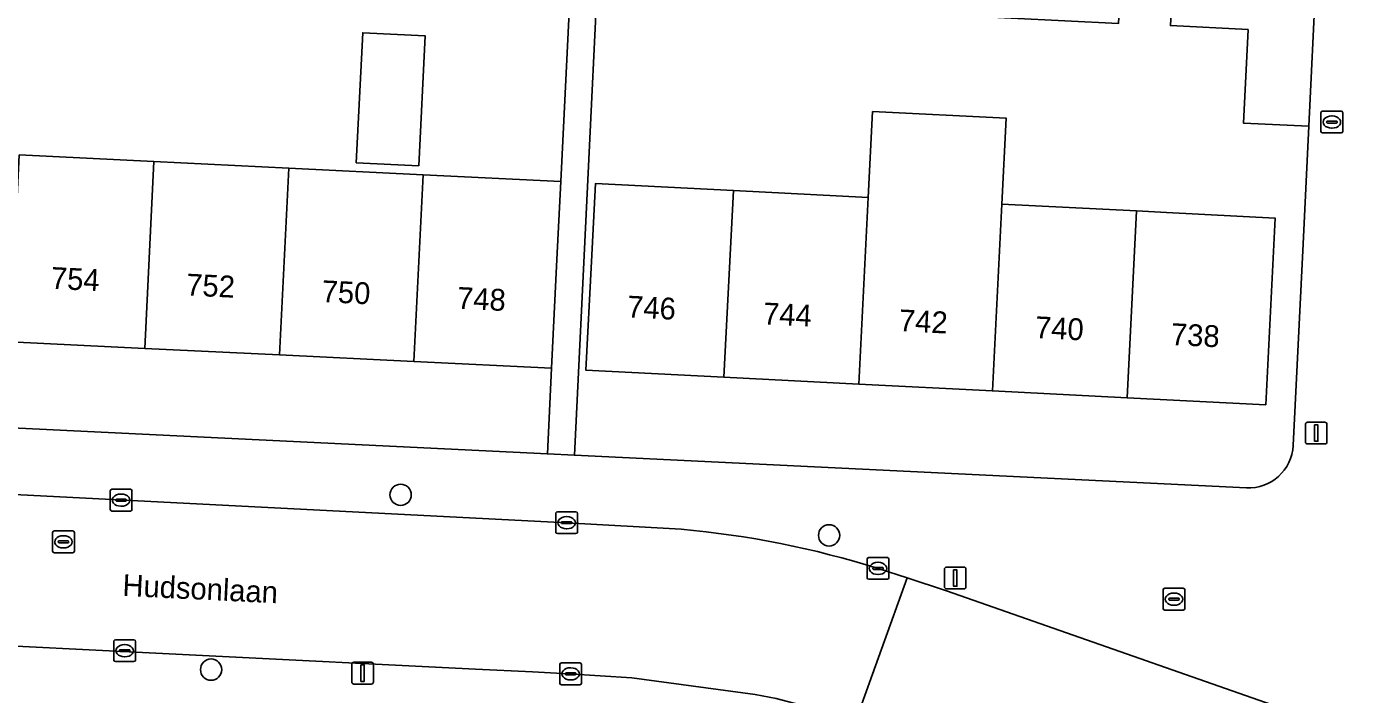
# Model space of a CAD drawing. Extents: x 161248 to 161848, y 384871 to 385383.
# Drawn here: x 161697.1 to 161757.8, y 385313.6 to 385344.3 of the extents above; entities that cross this region are included whole.
import ezdxf

# ---------------------------------------------------------------- set-up
doc = ezdxf.new("R2010")
doc.units = 0
for name, color, linetype in [('IMGEO_Boom', 7, 'Continuous'), ('IMGEO_Brandkraan', 7, 'Continuous'), ('IMGEO_Erf', 7, 'Continuous'), ('IMGEO_Kolk', 7, 'Continuous'), ('IMGEO_Lichtmast', 7, 'Continuous'), ('IMGEO_Muur', 7, 'Continuous'), ('IMGEO_Openbare_ruimte_label', 7, 'Continuous'), ('IMGEO_Pand', 7, 'Continuous'), ('IMGEO_Pand_nummerreeks', 7, 'Continuous'), ('IMGEO_Rijbaan_lokaal_open', 7, 'Continuous'), ('IMGEO_Rioolput', 7, 'Continuous'), ('IMGEO_Voetpad_open', 7, 'Continuous')]:
    doc.layers.add(name, color=color, linetype=linetype)

msp = doc.modelspace()

# ---------------------------------------------------------------- linework, layer by layer
at = {"layer": 'IMGEO_Boom'}
for centre in [(161714.232, 385322.779), (161733.904, 385320.919), (161705.532, 385314.757)]:
    msp.add_circle(centre, 0.489, dxfattribs=at)
at = {"layer": 'IMGEO_Brandkraan'}
for p, q in [((161756.486, 385339.456), (161756.486, 385340.308)), ((161756.561, 385340.382), (161757.413, 385340.382)), ((161756.788, 385339.925), (161757.186, 385339.925)), ((161756.974, 385340.162), (161756.999, 385340.162)), ((161757.487, 385340.308), (161757.487, 385339.456)), ((161757.413, 385339.382), (161756.561, 385339.382)), ((161756.745, 385339.876), (161756.745, 385339.888)), ((161757.183, 385339.839), (161756.785, 385339.839)), ((161756.997, 385339.602), (161756.972, 385339.602)), ((161757.229, 385339.888), (161757.229, 385339.876))]:
    msp.add_line(p, q, dxfattribs=at)
for points in [[(161756.486, 385339.456), (161756.486, 385340.308)], [(161756.561, 385340.382), (161757.413, 385340.382)], [(161757.487, 385340.308), (161757.487, 385339.456)], [(161757.413, 385339.382), (161756.561, 385339.382)]]:
    msp.add_lwpolyline(points, dxfattribs=at)
for centre, radius, start, end in [((161756.563, 385340.306), 0.0765, 91.55205, 178.44795), ((161756.563, 385340.306), 0.0765, 91.55205, 178.44795), ((161756.785, 385339.885), 0.0403, 85.87752, 175.75265), ((161757.19, 385339.887), 0.0386, 1.73085, 96.63898), ((161757.411, 385340.306), 0.0765, 1.55205, 88.44795), ((161757.411, 385340.306), 0.0765, 1.55205, 88.44795), ((161756.563, 385339.458), 0.0765, 181.55205, 268.44795), ((161756.563, 385339.458), 0.0765, 181.55205, 268.44795), ((161756.782, 385339.875), 0.0366, 178.93798, 274.71019), ((161757.186, 385339.882), 0.043, 264.86636, 352.45326), ((161757.411, 385339.458), 0.0765, 271.55205, 358.44795), ((161757.411, 385339.458), 0.0765, 271.55205, 358.44795)]:
    msp.add_arc(centre, radius, start, end, dxfattribs=at)
for centre, major_axis, ratio, start_param, end_param in [((161756.973, 385339.882), (-0.387, 0.002), 0.722429, 4.712389, 7.853982), ((161756.998, 385339.882), (-0.39, 0.002), 0.717154, 1.570796, 4.712389)]:
    msp.add_ellipse(centre, major_axis=major_axis, ratio=ratio, start_param=start_param, end_param=end_param, dxfattribs=at)
at = {"layer": 'IMGEO_Erf'}
for points in [[(161696.721, 385338.378), (161702.902, 385338.074), (161709.093, 385337.77), (161715.265, 385337.467), (161721.585, 385337.157), (161722.12, 385348.045), (161720.812, 385348.109), (161720.693, 385345.737), (161715.683, 385345.987), (161710.812, 385346.23), (161710.93, 385348.602), (161708.423, 385348.742), (161708.306, 385346.395), (161703.323, 385346.644), (161698.423, 385346.889), (161698.54, 385349.236), (161696.085, 385349.356)], [(161753.136, 385344.129), (161749.573, 385344.309), (161749.695, 385346.715), (161747.316, 385346.801), (161747.197, 385344.408), (161742.269, 385344.654), (161737.321, 385344.901), (161737.441, 385347.294), (161734.933, 385347.408), (161734.814, 385345.028), (161729.948, 385345.271), (161724.933, 385345.521), (161725.052, 385347.902), (161723.352, 385347.985), (161722.21, 385324.594), (161753.061, 385323.097)], [(161755.21, 385325.045), (161755.662, 385334.299), (161755.924, 385339.692), (161752.927, 385339.838), (161753.136, 385344.129)], [(161668.953, 385327.177), (161720.973, 385324.654), (161721.164, 385328.583), (161714.844, 385328.893), (161708.673, 385329.196), (161702.481, 385329.5), (161696.3, 385329.804)]]:
    msp.add_lwpolyline(points, dxfattribs=at)
for points in [[(161715.073, 385337.874), (161712.198, 385338.015), (161712.491, 385343.977), (161715.365, 385343.836)], [(161754.381, 385335.48), (161753.948, 385326.914), (161747.592, 385327.236), (161741.404, 385327.549), (161735.266, 385327.859), (161729.078, 385328.172), (161722.742, 385328.493), (161722.995, 385333.487), (161723.176, 385337.059), (161729.514, 385336.738), (161735.701, 385336.425), (161735.9, 385340.367), (161742.036, 385340.057), (161741.837, 385336.115), (161748.024, 385335.802), (161749.388, 385335.733)]]:
    msp.add_lwpolyline(points, close=True, dxfattribs=at)
msp.add_arc((161753.161, 385325.146), 2.051, 267.19239, 357.19022, dxfattribs=at)
at = {"layer": 'IMGEO_Kolk'}
for p, q in [((161700.898, 385322.11), (161700.898, 385322.962)), ((161700.973, 385323.036), (161701.825, 385323.036)), ((161701.899, 385322.962), (161701.899, 385322.11)), ((161701.157, 385322.53), (161701.157, 385322.542)), ((161701.595, 385322.493), (161701.197, 385322.493)), ((161701.2, 385322.579), (161701.598, 385322.579)), ((161701.386, 385322.816), (161701.411, 385322.816)), ((161701.641, 385322.542), (161701.641, 385322.53)), ((161701.825, 385322.036), (161700.973, 385322.036)), ((161701.409, 385322.256), (161701.384, 385322.256)), ((161721.354, 385321.073), (161721.354, 385321.925)), ((161721.429, 385321.999), (161722.281, 385321.999)), ((161721.842, 385321.779), (161721.867, 385321.779)), ((161722.355, 385321.925), (161722.355, 385321.073)), ((161721.613, 385321.493), (161721.613, 385321.505)), ((161722.051, 385321.456), (161721.653, 385321.456)), ((161721.656, 385321.542), (161722.054, 385321.542)), ((161721.865, 385321.219), (161721.84, 385321.219)), ((161722.097, 385321.505), (161722.097, 385321.493)), ((161722.281, 385320.999), (161721.429, 385320.999)), ((161735.725, 385319.902), (161736.577, 385319.902)), ((161735.65, 385318.976), (161735.65, 385319.828)), ((161735.909, 385319.396), (161735.909, 385319.408)), ((161736.347, 385319.359), (161735.949, 385319.359)), ((161735.952, 385319.445), (161736.35, 385319.445)), ((161736.138, 385319.682), (161736.163, 385319.682)), ((161736.393, 385319.408), (161736.393, 385319.396)), ((161736.651, 385319.828), (161736.651, 385318.976)), ((161736.577, 385318.902), (161735.725, 385318.902)), ((161736.161, 385319.122), (161736.136, 385319.122)), ((161701.063, 385315.2), (161701.063, 385316.052)), ((161701.138, 385316.126), (161701.99, 385316.126)), ((161701.322, 385315.62), (161701.322, 385315.632)), ((161701.365, 385315.669), (161701.763, 385315.669)), ((161701.551, 385315.906), (161701.576, 385315.906)), ((161701.806, 385315.632), (161701.806, 385315.62)), ((161702.064, 385316.052), (161702.064, 385315.2)), ((161701.99, 385315.126), (161701.138, 385315.126)), ((161701.76, 385315.583), (161701.362, 385315.583)), ((161701.574, 385315.346), (161701.549, 385315.346)), ((161721.614, 385315.063), (161722.466, 385315.063)), ((161721.539, 385314.137), (161721.539, 385314.989)), ((161721.798, 385314.557), (161721.798, 385314.569)), ((161722.236, 385314.52), (161721.838, 385314.52)), ((161721.841, 385314.606), (161722.239, 385314.606)), ((161722.027, 385314.843), (161722.052, 385314.843)), ((161722.282, 385314.569), (161722.282, 385314.557)), ((161722.54, 385314.989), (161722.54, 385314.137)), ((161722.466, 385314.063), (161721.614, 385314.063)), ((161722.05, 385314.283), (161722.025, 385314.283))]:
    msp.add_line(p, q, dxfattribs=at)
for points in [[(161700.898, 385322.11), (161700.898, 385322.962)], [(161700.973, 385323.036), (161701.825, 385323.036)], [(161701.899, 385322.962), (161701.899, 385322.11)], [(161701.825, 385322.036), (161700.973, 385322.036)], [(161721.354, 385321.073), (161721.354, 385321.925)], [(161721.429, 385321.999), (161722.281, 385321.999)], [(161722.355, 385321.925), (161722.355, 385321.073)], [(161722.281, 385320.999), (161721.429, 385320.999)], [(161735.725, 385319.902), (161736.577, 385319.902)], [(161735.65, 385318.976), (161735.65, 385319.828)], [(161736.651, 385319.828), (161736.651, 385318.976)], [(161736.577, 385318.902), (161735.725, 385318.902)], [(161701.063, 385315.2), (161701.063, 385316.052)], [(161701.138, 385316.126), (161701.99, 385316.126)], [(161702.064, 385316.052), (161702.064, 385315.2)], [(161701.99, 385315.126), (161701.138, 385315.126)], [(161721.614, 385315.063), (161722.466, 385315.063)], [(161721.539, 385314.137), (161721.539, 385314.989)], [(161722.54, 385314.989), (161722.54, 385314.137)], [(161722.466, 385314.063), (161721.614, 385314.063)]]:
    msp.add_lwpolyline(points, dxfattribs=at)
for centre, radius, start, end in [((161700.975, 385322.96), 0.0765, 91.55205, 178.44795), ((161700.975, 385322.96), 0.0765, 91.55205, 178.44795), ((161701.823, 385322.96), 0.0765, 1.55205, 88.44795), ((161701.823, 385322.96), 0.0765, 1.55205, 88.44795), ((161701.197, 385322.539), 0.0403, 85.87752, 175.75265), ((161701.194, 385322.529), 0.0366, 178.93798, 274.71019), ((161701.598, 385322.536), 0.043, 264.86636, 352.45326), ((161701.602, 385322.541), 0.0386, 1.73085, 96.63898), ((161700.975, 385322.112), 0.0765, 181.55205, 268.44795), ((161700.975, 385322.112), 0.0765, 181.55205, 268.44795), ((161701.823, 385322.112), 0.0765, 271.55205, 358.44795), ((161701.823, 385322.112), 0.0765, 271.55205, 358.44795), ((161721.431, 385321.923), 0.0765, 91.55205, 178.44795), ((161721.431, 385321.923), 0.0765, 91.55205, 178.44795), ((161722.279, 385321.923), 0.0765, 1.55205, 88.44795), ((161722.279, 385321.923), 0.0765, 1.55205, 88.44795), ((161721.653, 385321.502), 0.0403, 85.87752, 175.75265), ((161721.65, 385321.492), 0.0366, 178.93798, 274.71019), ((161722.054, 385321.499), 0.043, 264.86636, 352.45326), ((161722.058, 385321.504), 0.0386, 1.73085, 96.63898), ((161721.431, 385321.075), 0.0765, 181.55205, 268.44795), ((161721.431, 385321.075), 0.0765, 181.55205, 268.44795), ((161722.279, 385321.075), 0.0765, 271.55205, 358.44795), ((161722.279, 385321.075), 0.0765, 271.55205, 358.44795), ((161735.727, 385319.826), 0.0765, 91.55205, 178.44795), ((161735.727, 385319.826), 0.0765, 91.55205, 178.44795), ((161736.575, 385319.826), 0.0765, 1.55205, 88.44795), ((161736.575, 385319.826), 0.0765, 1.55205, 88.44795), ((161735.949, 385319.405), 0.0403, 85.87752, 175.75265), ((161735.946, 385319.395), 0.0366, 178.93798, 274.71019), ((161736.35, 385319.402), 0.043, 264.86636, 352.45326), ((161736.354, 385319.407), 0.0386, 1.73085, 96.63898), ((161735.727, 385318.978), 0.0765, 181.55205, 268.44795), ((161735.727, 385318.978), 0.0765, 181.55205, 268.44795), ((161736.575, 385318.978), 0.0765, 271.55205, 358.44795), ((161736.575, 385318.978), 0.0765, 271.55205, 358.44795), ((161701.14, 385316.05), 0.0765, 91.55205, 178.44795), ((161701.14, 385316.05), 0.0765, 91.55205, 178.44795), ((161701.362, 385315.629), 0.0403, 85.87752, 175.75265), ((161701.359, 385315.619), 0.0366, 178.93798, 274.71019), ((161701.763, 385315.626), 0.043, 264.86636, 352.45326), ((161701.767, 385315.631), 0.0386, 1.73085, 96.63898), ((161701.988, 385316.05), 0.0765, 1.55205, 88.44795), ((161701.988, 385316.05), 0.0765, 1.55205, 88.44795), ((161701.14, 385315.202), 0.0765, 181.55205, 268.44795), ((161701.14, 385315.202), 0.0765, 181.55205, 268.44795), ((161701.988, 385315.202), 0.0765, 271.55205, 358.44795), ((161701.988, 385315.202), 0.0765, 271.55205, 358.44795), ((161721.616, 385314.987), 0.0765, 91.55205, 178.44795), ((161721.616, 385314.987), 0.0765, 91.55205, 178.44795), ((161722.464, 385314.987), 0.0765, 1.55205, 88.44795), ((161722.464, 385314.987), 0.0765, 1.55205, 88.44795), ((161721.838, 385314.566), 0.0403, 85.87752, 175.75265), ((161721.835, 385314.556), 0.0366, 178.93798, 274.71019), ((161722.239, 385314.563), 0.043, 264.86636, 352.45326), ((161722.243, 385314.568), 0.0386, 1.73085, 96.63898), ((161721.616, 385314.139), 0.0765, 181.55205, 268.44795), ((161721.616, 385314.139), 0.0765, 181.55205, 268.44795), ((161722.464, 385314.139), 0.0765, 271.55205, 358.44795), ((161722.464, 385314.139), 0.0765, 271.55205, 358.44795)]:
    msp.add_arc(centre, radius, start, end, dxfattribs=at)
for centre, major_axis, ratio, start_param, end_param in [((161701.385, 385322.536), (-0.387, 0.002), 0.722429, 4.712389, 7.853982), ((161701.41, 385322.536), (-0.39, 0.002), 0.717154, 1.570796, 4.712389), ((161721.841, 385321.499), (-0.387, 0.002), 0.722429, 4.712389, 7.853982), ((161721.866, 385321.499), (-0.39, 0.002), 0.717154, 1.570796, 4.712389), ((161736.137, 385319.402), (-0.387, 0.002), 0.722429, 4.712389, 7.853982), ((161736.162, 385319.402), (-0.39, 0.002), 0.717154, 1.570796, 4.712389), ((161701.55, 385315.626), (-0.387, 0.002), 0.722429, 4.712389, 7.853982), ((161701.575, 385315.626), (-0.39, 0.002), 0.717154, 1.570796, 4.712389), ((161722.026, 385314.563), (-0.387, 0.002), 0.722429, 4.712389, 7.853982), ((161722.051, 385314.563), (-0.39, 0.002), 0.717154, 1.570796, 4.712389)]:
    msp.add_ellipse(centre, major_axis=major_axis, ratio=ratio, start_param=start_param, end_param=end_param, dxfattribs=at)
at = {"layer": 'IMGEO_Lichtmast'}
for p, q in [((161755.772, 385325.211), (161755.772, 385326.011)), ((161755.772, 385326.011), (161755.772, 385325.211)), ((161755.872, 385326.111), (161756.662, 385326.111)), ((161756.662, 385326.111), (161755.872, 385326.111)), ((161756.762, 385326.011), (161756.762, 385325.211)), ((161756.762, 385325.211), (161756.762, 385326.011)), ((161756.662, 385325.111), (161755.872, 385325.111)), ((161755.872, 385325.111), (161756.662, 385325.111)), ((161739.198, 385318.56), (161739.198, 385319.36)), ((161739.198, 385319.36), (161739.198, 385318.56)), ((161739.298, 385319.46), (161740.088, 385319.46)), ((161740.088, 385319.46), (161739.298, 385319.46)), ((161740.188, 385319.36), (161740.188, 385318.56)), ((161740.188, 385318.56), (161740.188, 385319.36)), ((161740.088, 385318.46), (161739.298, 385318.46)), ((161739.298, 385318.46), (161740.088, 385318.46)), ((161712.09, 385315.096), (161712.88, 385315.096)), ((161712.88, 385315.096), (161712.09, 385315.096)), ((161711.99, 385314.196), (161711.99, 385314.996)), ((161711.99, 385314.996), (161711.99, 385314.196)), ((161712.98, 385314.996), (161712.98, 385314.196)), ((161712.98, 385314.196), (161712.98, 385314.996)), ((161712.88, 385314.096), (161712.09, 385314.096)), ((161712.09, 385314.096), (161712.88, 385314.096))]:
    msp.add_line(p, q, dxfattribs=at)
for points in [[(161756.192, 385325.986), (161756.342, 385325.986), (161756.342, 385325.236), (161756.192, 385325.236), (161756.192, 385325.986)], [(161739.618, 385319.335), (161739.768, 385319.335), (161739.768, 385318.585), (161739.618, 385318.585), (161739.618, 385319.335)], [(161712.41, 385314.971), (161712.56, 385314.971), (161712.56, 385314.221), (161712.41, 385314.221), (161712.41, 385314.971)]]:
    msp.add_lwpolyline(points, dxfattribs=at)
for centre, start, end in [((161755.872, 385326.011), 90, 180), ((161755.872, 385326.011), 90, 180), ((161756.662, 385326.011), 0, 90), ((161756.662, 385326.011), 360, 90), ((161755.872, 385325.211), 180, 270), ((161755.872, 385325.211), 180, 270), ((161756.662, 385325.211), 270, 0), ((161756.662, 385325.211), 270, 0), ((161739.298, 385319.36), 90, 180), ((161739.298, 385319.36), 90, 180), ((161740.088, 385319.36), 0, 90), ((161740.088, 385319.36), 360, 90), ((161739.298, 385318.56), 180, 270), ((161739.298, 385318.56), 180, 270), ((161740.088, 385318.56), 270, 0), ((161740.088, 385318.56), 270, 0), ((161712.09, 385314.996), 90, 180), ((161712.09, 385314.996), 90, 180), ((161712.88, 385314.996), 0, 90), ((161712.88, 385314.996), 360, 90), ((161712.09, 385314.196), 180, 270), ((161712.09, 385314.196), 180, 270), ((161712.88, 385314.196), 270, 0), ((161712.88, 385314.196), 270, 0)]:
    msp.add_arc(centre, 0.1, start, end, dxfattribs=at)
at = {"layer": 'IMGEO_Muur'}
msp.add_lwpolyline([(161755.924, 385339.692), (161755.662, 385334.299)], dxfattribs=at)
at = {"layer": 'IMGEO_Pand'}
for points in [[(161756.248, 385346.384), (161749.695, 385346.715), (161749.573, 385344.309), (161753.136, 385344.129), (161752.927, 385339.838), (161755.924, 385339.692)], [(161715.073, 385337.874), (161715.365, 385343.836), (161712.491, 385343.977), (161712.198, 385338.015)], [(161741.837, 385336.115), (161742.036, 385340.057), (161735.9, 385340.367), (161735.701, 385336.425), (161735.266, 385327.859), (161741.404, 385327.549)], [(161702.902, 385338.074), (161696.721, 385338.378), (161696.3, 385329.804), (161702.481, 385329.5)], [(161702.481, 385329.5), (161708.673, 385329.196), (161709.093, 385337.77), (161702.902, 385338.074)], [(161715.265, 385337.467), (161709.093, 385337.77), (161708.673, 385329.196), (161714.844, 385328.893)], [(161714.844, 385328.893), (161721.164, 385328.583), (161721.409, 385333.577), (161721.585, 385337.157), (161715.265, 385337.467)], [(161729.514, 385336.738), (161723.176, 385337.059), (161722.995, 385333.487), (161722.742, 385328.493), (161729.078, 385328.172)], [(161735.701, 385336.425), (161729.514, 385336.738), (161729.078, 385328.172), (161735.266, 385327.859)], [(161748.024, 385335.802), (161741.837, 385336.115), (161741.404, 385327.549), (161747.592, 385327.236)], [(161747.592, 385327.236), (161753.948, 385326.914), (161754.381, 385335.48), (161749.388, 385335.733), (161748.024, 385335.802)]]:
    msp.add_lwpolyline(points, close=True, dxfattribs=at)
at = {"layer": 'IMGEO_Rijbaan_lokaal_open'}
for points in [[(161727.107, 385321.198), (161721.855, 385321.499), (161692.318, 385323.006), (161691.971, 385316.06), (161717.671, 385314.779), (161720.287, 385314.65), (161721.935, 385314.567), (161724.841, 385314.378), (161730.509, 385313.623), (161731.466, 385313.432), (161734.373, 385312.669), (161735.132, 385312.431), (161737.495, 385318.967), (161736.151, 385319.402)], [(161757.612, 385311.967), (161739.3, 385318.374), (161737.495, 385318.967), (161735.132, 385312.431)]]:
    msp.add_lwpolyline(points, dxfattribs=at)
msp.add_arc((161723.296, 385278.338), 43.029, 72.61737, 84.91875, dxfattribs=at)
at = {"layer": 'IMGEO_Rioolput'}
for p, q in [((161698.326, 385321.123), (161699.178, 385321.123)), ((161698.251, 385320.197), (161698.251, 385321.049)), ((161698.51, 385320.617), (161698.51, 385320.629)), ((161698.948, 385320.58), (161698.55, 385320.58)), ((161698.553, 385320.666), (161698.951, 385320.666)), ((161698.739, 385320.903), (161698.764, 385320.903)), ((161698.994, 385320.629), (161698.994, 385320.617)), ((161699.252, 385321.049), (161699.252, 385320.197)), ((161699.178, 385320.123), (161698.326, 385320.123)), ((161698.762, 385320.343), (161698.737, 385320.343)), ((161749.239, 385317.566), (161749.239, 385318.418)), ((161749.314, 385318.492), (161750.166, 385318.492)), ((161749.727, 385318.272), (161749.752, 385318.272)), ((161750.24, 385318.418), (161750.24, 385317.566)), ((161750.166, 385317.492), (161749.314, 385317.492)), ((161749.498, 385317.986), (161749.498, 385317.998)), ((161749.936, 385317.949), (161749.538, 385317.949)), ((161749.541, 385318.035), (161749.939, 385318.035)), ((161749.75, 385317.712), (161749.725, 385317.712)), ((161749.982, 385317.998), (161749.982, 385317.986))]:
    msp.add_line(p, q, dxfattribs=at)
for points in [[(161698.326, 385321.123), (161699.178, 385321.123)], [(161698.251, 385320.197), (161698.251, 385321.049)], [(161699.252, 385321.049), (161699.252, 385320.197)], [(161699.178, 385320.123), (161698.326, 385320.123)], [(161749.239, 385317.566), (161749.239, 385318.418)], [(161749.314, 385318.492), (161750.166, 385318.492)], [(161750.24, 385318.418), (161750.24, 385317.566)], [(161750.166, 385317.492), (161749.314, 385317.492)]]:
    msp.add_lwpolyline(points, dxfattribs=at)
for centre, radius, start, end in [((161698.328, 385321.047), 0.0765, 91.55205, 178.44795), ((161698.328, 385321.047), 0.0765, 91.55205, 178.44795), ((161699.176, 385321.047), 0.0765, 1.55205, 88.44795), ((161699.176, 385321.047), 0.0765, 1.55205, 88.44795), ((161698.55, 385320.626), 0.0403, 85.87752, 175.75265), ((161698.547, 385320.616), 0.0366, 178.93798, 274.71019), ((161698.951, 385320.623), 0.043, 264.86636, 352.45326), ((161698.955, 385320.628), 0.0386, 1.73085, 96.63898), ((161698.328, 385320.199), 0.0765, 181.55205, 268.44795), ((161698.328, 385320.199), 0.0765, 181.55205, 268.44795), ((161699.176, 385320.199), 0.0765, 271.55205, 358.44795), ((161699.176, 385320.199), 0.0765, 271.55205, 358.44795), ((161749.316, 385318.416), 0.0765, 91.55205, 178.44795), ((161749.316, 385318.416), 0.0765, 91.55205, 178.44795), ((161750.164, 385318.416), 0.0765, 1.55205, 88.44795), ((161750.164, 385318.416), 0.0765, 1.55205, 88.44795), ((161749.316, 385317.568), 0.0765, 181.55205, 268.44795), ((161749.316, 385317.568), 0.0765, 181.55205, 268.44795), ((161749.538, 385317.995), 0.0403, 85.87752, 175.75265), ((161749.535, 385317.985), 0.0366, 178.93798, 274.71019), ((161749.939, 385317.992), 0.043, 264.86636, 352.45326), ((161749.943, 385317.997), 0.0386, 1.73085, 96.63898), ((161750.164, 385317.568), 0.0765, 271.55205, 358.44795), ((161750.164, 385317.568), 0.0765, 271.55205, 358.44795)]:
    msp.add_arc(centre, radius, start, end, dxfattribs=at)
for centre, major_axis, ratio, start_param, end_param in [((161698.738, 385320.623), (-0.387, 0.002), 0.722429, 4.712389, 7.853982), ((161698.763, 385320.623), (-0.39, 0.002), 0.717154, 1.570796, 4.712389), ((161749.726, 385317.992), (-0.387, 0.002), 0.722429, 4.712389, 7.853982), ((161749.751, 385317.992), (-0.39, 0.002), 0.717154, 1.570796, 4.712389)]:
    msp.add_ellipse(centre, major_axis=major_axis, ratio=ratio, start_param=start_param, end_param=end_param, dxfattribs=at)
at = {"layer": 'IMGEO_Voetpad_open'}
for points in [[(161758.943, 385340.315), (161759.231, 385346.211), (161759.278, 385347.179), (161759.61, 385354.002), (161756.608, 385353.777), (161756.294, 385347.324), (161756.248, 385346.384), (161755.924, 385339.692), (161755.662, 385334.299), (161755.21, 385325.045)], [(161753.061, 385323.097), (161722.21, 385324.594), (161720.973, 385324.654), (161668.953, 385327.177), (161657.297, 385327.746)], [(161657.672, 385324.773), (161689.542, 385323.147), (161692.318, 385323.006), (161721.855, 385321.499), (161727.107, 385321.198)], [(161736.151, 385319.402), (161737.495, 385318.967), (161739.3, 385318.374), (161757.612, 385311.967), (161759.283, 385311.353), (161761.622, 385310.562), (161765.379, 385309.235), (161771.298, 385307.168), (161776.197, 385305.434)], [(161724.841, 385314.378), (161721.935, 385314.567), (161720.287, 385314.65), (161717.671, 385314.779), (161691.971, 385316.06), (161689.194, 385316.198), (161662.442, 385317.53), (161658.911, 385317.706), (161658.095, 385317.747)], [(161731.466, 385313.432), (161730.509, 385313.623), (161724.841, 385314.378)]]:
    msp.add_lwpolyline(points, dxfattribs=at)
msp.add_lwpolyline([(161723.352, 385347.985), (161722.12, 385348.045), (161721.585, 385337.157), (161721.409, 385333.577), (161721.164, 385328.583), (161720.973, 385324.654), (161722.21, 385324.594)], close=True, dxfattribs=at)
for centre, radius, start, end in [((161753.161, 385325.146), 2.051, 267.19239, 357.19022), ((161723.296, 385278.338), 43.029, 72.61737, 84.91875)]:
    msp.add_arc(centre, radius, start, end, dxfattribs=at)

# ---------------------------------------------------------------- texts
at = {"layer": 'IMGEO_Openbare_ruimte_label'}
msp.add_text('Hudsonlaan', height=1, rotation=357.24917, dxfattribs=at).set_placement((161701.445, 385318.144))
at = {"layer": 'IMGEO_Pand_nummerreeks'}
for s, rotation, p in [('754', 357.18921, (161698.159, 385332.235)), ('752', 357.18921, (161704.37, 385331.93)), ('750', 357.18921, (161710.591, 385331.625)), ('748', 357.18921, (161716.806, 385331.32)), ('746', 357.10335, (161724.613, 385330.921)), ('744', 357.10335, (161730.854, 385330.606)), ('742', 357.10083, (161737.093, 385330.29)), ('740', 357.10335, (161743.34, 385329.974)), ('738', 357.10335, (161749.581, 385329.658))]:
    msp.add_text(s, height=1, rotation=rotation, dxfattribs=at).set_placement(p)

doc.saveas('drawing.dxf')
